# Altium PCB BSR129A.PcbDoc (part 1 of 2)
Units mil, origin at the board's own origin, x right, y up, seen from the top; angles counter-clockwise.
Board outline 2165.87 x 2165.5 mil, 2 copper layers (Top Layer, Bottom Layer), stack 61.2 mil thick; 64 components, 16 nets, 93 pads, 184 vias.
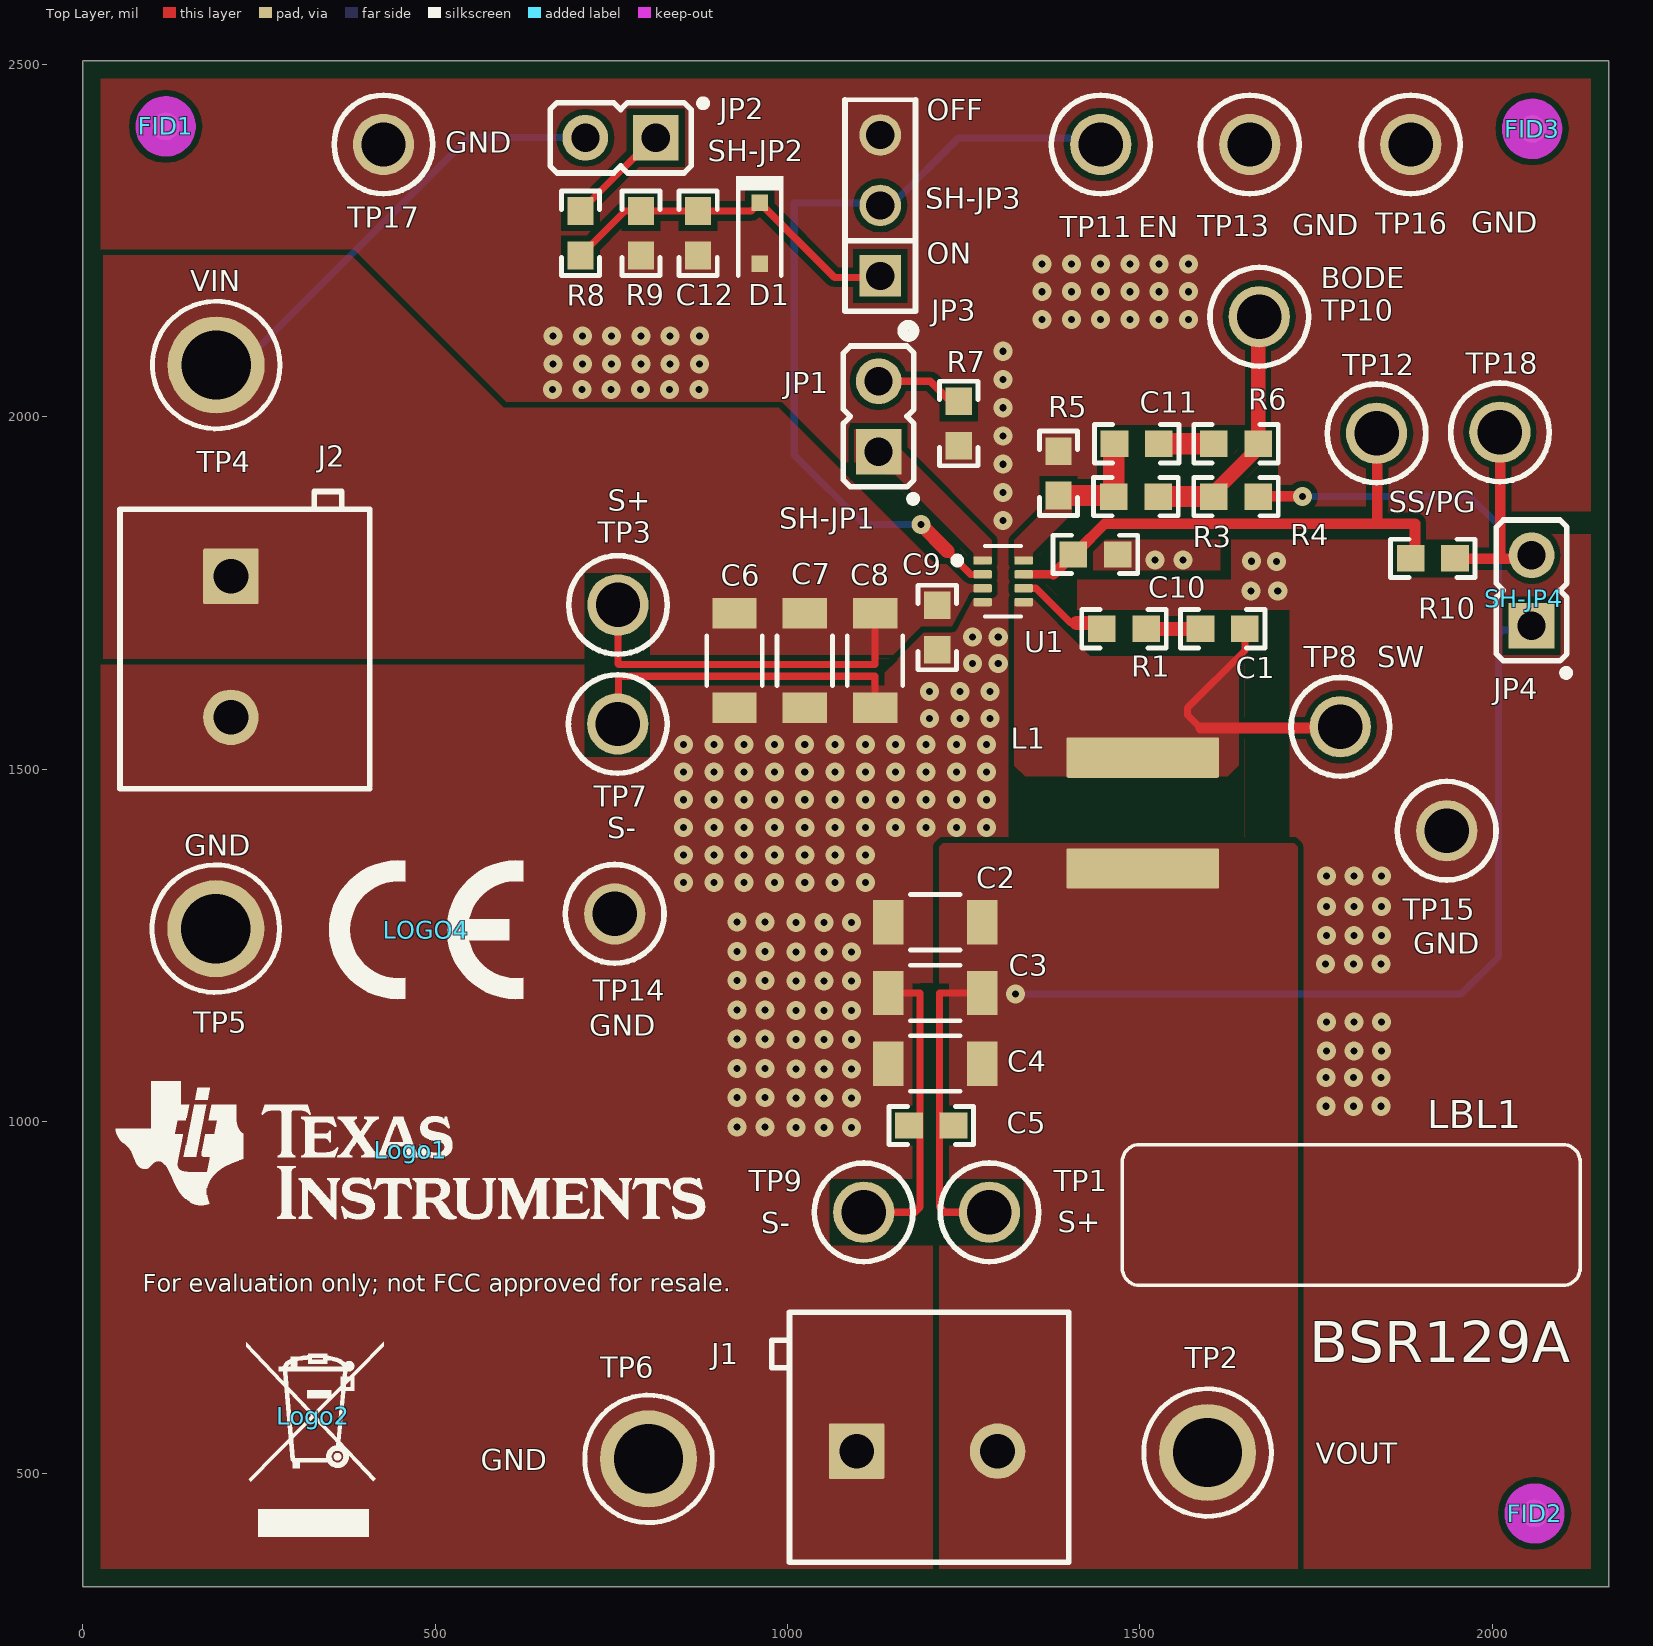
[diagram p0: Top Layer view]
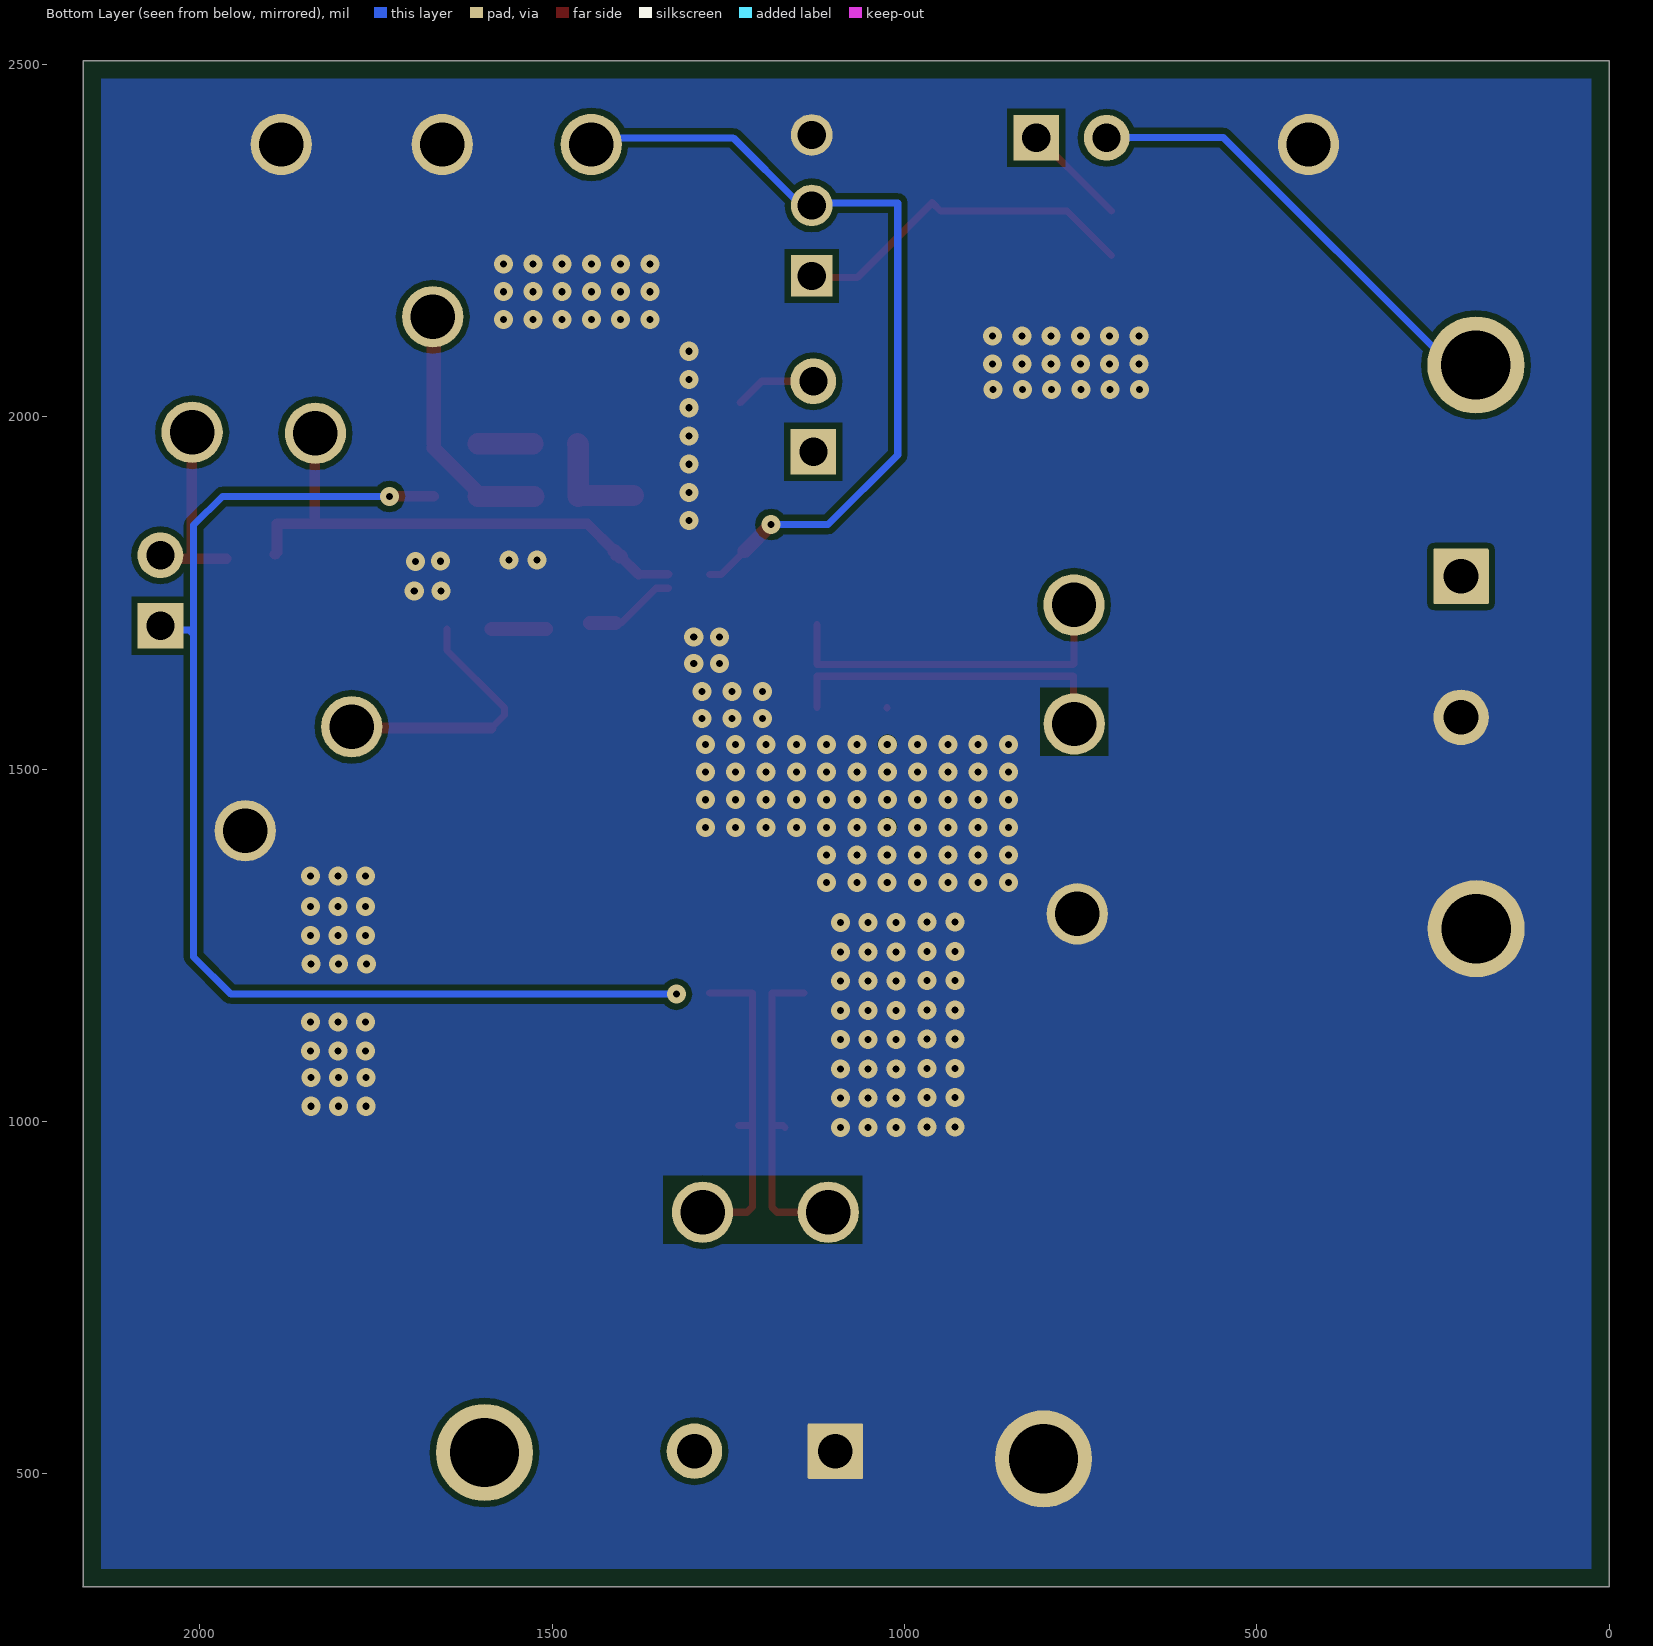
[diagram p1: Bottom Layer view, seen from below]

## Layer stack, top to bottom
Top Solder: solder mask 0.4, Solder Resist, Dk 3.5
Top Layer: signal copper 2.8
Dielectric1: core 55.6, FR-4 High Tg, Dk 4.8
Bottom Layer: signal copper 2.8
Bottom Solder: solder mask 0.4, Solder Resist, Dk 3.5

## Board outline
0,339.65 0,2505 2165.35,2505 2165.35,339.65 2165.87,339.5

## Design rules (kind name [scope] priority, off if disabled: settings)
AcuteAngle [All] p1: minimum=4.50000000000000E+0001 checktracksonly=FALSE
AssemblyTestPointUsage [All] p1: valid=2
BoardOutlineClearance BoardOutlineClearance_MountingHoles [OnCopper and InComponentClass('Mounting Holes')] p1: gap=40 ignorepadtopadclearanceinfootprint=FALSE
BoardOutlineClearance BoardOutlineClearance_Poly [OnCopper and IsPoly] p2: gap=25 ignorepadtopadclearanceinfootprint=FALSE
BoardOutlineClearance [OnCopper and Not InComponentClass('Logo') and not InComponentClass('FiducialMark') and not InRegion(1000,500,4000,800) and not InPoly] p3: gap=75 ignorepadtopadclearanceinfootprint=FALSE
Clearance Clearance_Keepouts [((IsTrack Or IsArc) And Not InPoly) And IsFree and IsKeepOut vs ((IsTrack Or IsArc) And Not InPoly) And IsFree and IsKeepOut] p1: gap=0 ignorepadtopadclearanceinfootprint=FALSE
Clearance Clearance_Poly [InPolygon] p2: gap=8.5 ignorepadtopadclearanceinfootprint=FALSE except(0: Arc-Hole Track-Hole SMDPad-Hole THPad-Hole Via-Hole Fill-Hole Poly-Hole Region-Hole Text-Hole)
Clearance [All] p3: gap=7 ignorepadtopadclearanceinfootprint=FALSE except(0: Arc-Hole Track-Hole SMDPad-Hole THPad-Hole Via-Hole Fill-Hole Poly-Hole Region-Hole Text-Hole)
ComponentClearance ComponentClearance_MountingHoles_FiducialMarks [InComponentClass('Mounting Holes') vs InComponentClass('FiducialMark')] p1: gap=50 collisioncheckmode=3 verticalgap=10 showdistances=FALSE
ComponentClearance ComponentClearance_Shunt [InComponentClass('Header') vs InComponentClass('Shunt')] p2: gap=0 collisioncheckmode=3 verticalgap=0 showdistances=FALSE
ComponentClearance ComponentClearance_Logo [InComponentClass('Logo')] p3: gap=50 collisioncheckmode=3 verticalgap=10 showdistances=FALSE
ComponentClearance ComponentClearance_ScrewToNut [(HasFootprint('NY PMS 440 0025 PH')) vs (HasFootprint('Keystone_1902C'))] p4: gap=5 collisioncheckmode=3 verticalgap=10 showdistances=FALSE
ComponentClearance ComponentClearance_MountingHoles [InComponentClass('Mounting Holes')] p5: gap=250 collisioncheckmode=3 verticalgap=100000 showdistances=FALSE
ComponentClearance ComponentClearance_SmallPassives [HasFootprint('0201*') or HasFootprint('0402*') or HasFootprint('0508') or HasFootprint('0603*') or HasFootprint('0612') or HasFootprint('0805*') or HasFootprint('0815*') or HasFootprint('0830*') or HasFootprint('1206*') or HasFootprint('1210*') or HasFootprint('1808*') or HasFootprint('1812*') or HasFootprint('1825*') or HasFootprint('2010*') or HasFootprint('2220*') or HasFootprint('2225*') or HasFootprint('2512*') or HasFootprint('2728*') or HasFootprint('3518*') vs HasFootprint('0201*') or HasFootprint('0402*') or HasFootprint('0508') or HasFootprint('0603*') or HasFootprint('0612') or HasFootprint('0805*') or HasFootprint('0815*') or HasFootprint('0830*') or HasFootprint('1206*') or HasFootprint('1210*') or HasFootprint('1808*') or HasFootprint('1812*') or HasFootprint('1825*') or HasFootprint('2010*') or HasFootprint('2220*') or HasFootprint('2225*') or HasFootprint('2512*') or HasFootprint('2728*') or HasFootprint('3518*')] p6: gap=14.96 collisioncheckmode=3 verticalgap=10 showdistances=FALSE
ComponentClearance ComponentClearance_THtoSMT [IsThruComponent vs IsSMTComponent] p7: gap=40 collisioncheckmode=3 verticalgap=30 showdistances=FALSE
ComponentClearance ComponentClearance_THtoTH [IsThruComponent vs IsThruComponent] p8: gap=30 collisioncheckmode=3 verticalgap=30 showdistances=FALSE
ComponentClearance [All] p9: gap=30 collisioncheckmode=3 verticalgap=10 showdistances=FALSE
DiffPairsRouting [All] p1: maxlimit=100 minlimit=10 mostfreqgap=10 toplayer_minwidth=15 toplayer_maxwidth=15 toplayer_prefwidth=15 bottomlayer_minwidth=15 bottomlayer_maxwidth=15 bottomlayer_prefwidth=15 maxuncoupledlength=1000
FabricationTestPointUsage TestPointUsage [All] p1: valid=2 allowmultiple=FALSE
FabricationTestpoint Testpoint [All] p1: side=3 testpointundercomponent=TRUE minsize=40 maxsize=100 preferedsize=60 minholesize=0 maxholesize=40 preferedholesize=32 testpointgrid=1 allowsidetop=TRUE allowsidebottom=TRUE usegrid=TRUE gridtolerance=0.01
FanoutControl Fanout_LCC [IsLCC] p1: bgadir=Out bgaviamode=Centered fanoutstyle=Auto fanoutdirection=Alternating viagrid=1 // Fanout_LCC (Default Rule)
FanoutControl Fanout_BGA [IsBGA] p2: bgadir=Out bgaviamode=Centered fanoutstyle=Auto fanoutdirection=Alternating viagrid=1 // Fanout_BGA (Default Rule)
FanoutControl Fanout_Default [All] p4: bgadir=Out bgaviamode=Centered fanoutstyle=Auto fanoutdirection=Alternating viagrid=1 // Fanout_Default (Default Rule)
FanoutControl Fanout_Small [(CompPinCount < 5)] p5: bgadir=Out bgaviamode=Centered fanoutstyle=Auto fanoutdirection=OutThenIn viagrid=1 // Fanout_Small (Default Rule)
HoleSize [All] p1: absolutevalues=TRUE maxlimit=251 minlimit=7.87 maxpercent=80.000 minpercent=20.000
MinimumAnnularRing MinimumAnnularRing_ThermalPadVias [IsVia and InAnyComponent] p1: minimumring=5.91
MinimumAnnularRing [All] p2: minimumring=6
MinimumSolderMaskSliver MinimumSolderMaskSliver_Logo [InComponentClass('Logo') vs InComponentClass('Logo')] p1: minsoldermaskwidth=0.7
MinimumSolderMaskSliver [All] p2: minsoldermaskwidth=3.94
PlaneClearance [All] p1: clearance=0
PlaneConnect [All] p1: planeconnectstyle=Direct reliefexpansion=10 reliefentries=2 reliefconductorwidth=10 reliefairgap=10
PolygonConnect [All] p1: connectstyle=Direct reliefconductorwidth=10 reliefentries=4 polygonreliefangle="90 Angle" airgapwidth=10
RoutingVias ThermalPadVias [IsVia and InAnyComponent] p1: holewidth=7.87 width=19.68 viastyle="Through Hole" minholewidth=7.87 minwidth=19.68 maxholewidth=12.99 maxwidth=23.62
RoutingVias [All] p2: holewidth=16 width=34 viastyle="Through Hole" minholewidth=7.87 minwidth=26 maxholewidth=40 maxwidth=65
SilkToBoardRegionClearance [Not ((IsComment or IsDesignator) And (Hide <> 'False')) and not InRegion(1000,500,4000,800)] p1:
SilkToSilkClearance SilkToSilkClearance_Pb-FreeLogo [(HasFootprint('Pb-Free_Overlay_Medium') OR HasFootprint('Pb-Free_Overlay_Small')) vs (HasFootprint('Pb-Free_Overlay_Medium') OR HasFootprint('Pb-Free_Overlay_Small'))] p1: silktosilkclearance=0
SilkToSilkClearance [All] p2: silktosilkclearance=4
SilkToSolderMaskClearance SilkToComponentPadClearance [(IsPad or IsFill or IsRegion) and InAnycomponent] p1: minsilkscreentomaskgap=2 clearancetoexposedcopper=TRUE
SilkToSolderMaskClearance "Silk to Solder Mask Opening" [All] p2: minsilkscreentomaskgap=0.5 clearancetoexposedcopper=TRUE
SolderMaskExpansion [All] p1: expansion=1.85
Width [All] p1: maxlimit=100 minlimit=3 preferedwidth=10 bottomlayer_minwidth=6 minimp=50.000000 maximp=50.000000 favimp=50.000000 checkconnectedcopper=TRUE
14 further rules are at their usual default settings.

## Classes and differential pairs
component class Label: LBL1
component class Shunt: SH-JP1 SH-JP2 SH-JP3 SH-JP4
component class FiducialMark: FID1 FID2 FID3
component class BSR129A_Hardware: FID1 FID2 FID3 LBL1 Logo1 Logo2 Logo3 LOGO4 LOGO7 SH-JP1 SH-JP2 SH-JP3 SH-JP4 ZZ1 ZZ2 ZZ3 ZZ4
component class Logo: Logo1
component class Header: JP1 JP2 JP3 JP4
component class BSR129A: 2 C1 C2 C3 C4 C5 C6 C7 C8 C9 C11 C12 D1 GND GND3 J1 J2 JP1 JP2 JP3 JP4 L1 R1 R3 R4 R5 R6 R7 R8 R9 R10 TP1 TP2 TP3 TP4 TP5 TP6 TP7 TP8 TP9 TP10 TP11 TP12 TP13 TP14 TP15 TP16 TP17 TP18 U1 VIN1 VOUT0
component class AssemblyNote: ZZ1 ZZ2 ZZ3 ZZ4

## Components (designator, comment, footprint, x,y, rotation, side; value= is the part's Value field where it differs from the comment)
C1 "C0603C104K5RACAUTO" 0603 1617.5,1699 r180 top value=0.1uF
C2 "C3216X5R1V226M160AC" 1206_180 1209.5,1282.5 r180 top value=22uF
C3 "C3216X5R1V226M160AC" 1206_180 1209.5,1182.25 r180 top value=22uF
C4 "C3216X5R1V226M160AC" 1206_180 1209.5,1082 r180 top value=22uF
C5 "C0603C104K5RACAUTO" 0603 1204,994.16 r180 top value=0.1uF
C6 "CGA5L1X7R1H106K160AC" 1206_190 924.75,1653.97 r270 top value=10uF
C7 "CGA5L1X7R1H106K160AC" 1206_190 1024.5,1653.97 r270 top value=10uF
C8 "CGA5L1X7R1H106K160AC" 1206_190 1124.25,1653.97 r270 top value=10uF
C9 "C0603C104K5RACAUTO" 0603 1212.5,1700.98 r270 top value=0.1uF
C10 "06035C333JAT2A" 0603 1437,1804.65 r0 top value=0.033uF
C11 "C0603C100J5GACTU" 0603 1495.47,1961.73 r180 top value=10pF
C12 "C0603C103J5RACTU" 0603 872.9,2260.45 r270 top value=0.01uF
D1 "Zener" SOD-323 960.5,2260.51 r270 top value=5.1V
FID1 "Fiducial" Fiducial10-20 117.37,2412.09 r0 top
FID2 "Fiducial" Fiducial10-20 2060.13,443.5 r0 top
FID3 "Fiducial" Fiducial10-20 2056.63,2408.59 r0 top
J1 "ED120/2DS" On-Shore_ED120_2DS 1198,532 r0 top
J2 "ED120/2DS" On-Shore_ED120_2DS 210,1673.5 r270 top
JP1 "PBC02SAAN" Sullins_PBC02SAAN 1129.27,2000.48 r180 top
JP2 "PBC02SAAN" Sullins_PBC02SAAN 763,2396 r270 top
JP3 "PEC03SAAN" CONN_PEC03SAAN 1131.5,2300 r90 top
JP4 "PBC02SAAN" Sullins_PBC02SAAN 2056,1753.5 r180 top
L1 "74439346068" WE-XHMI_6060 1504,1437.5 r270 top value=6.8uH
LBL1 "THT-14-423-10" Label_650x200 1800,867.16 r0 top
Logo1 "Texas Instruments" TI_Stacked_Overlay_Small 465,959 r0 top
Logo2 "WEEE logo" WEEE_Minimum 327.15,582.5 r0 top
Logo3 "FCC disclaimer" FCC_disclaimer 5235,-1337.5 r90 top
LOGO4 "CE Mark" CE_Mark_5mm 487,1272 r0 top
R1 "RC0603JR-070RL" 0603 1477.5,1699 r0 top value=0
R3 "RC0603FR-0749R9L" 0603 1636.47,1886.73 r0 top value=49.9
R4 "RC0603FR-0753K6L" 0603 1494.48,1886.73 r0 top value=53.6k
R5 "RC0603FR-0710K2L" 0603 1384.48,1919.73 r270 top value=10.2k
R6 "RC0603JR-070RL" 0603 1636.48,1961.73 r0 top value=0
R7 "RC0603JR-070RL" 0603 1243,1990.5 r90 top value=0
R8 "RC0603FR-0749K9L" 0603 706.17,2260.45 r90 top value=49.9k
R9 "RC0603FR-0749K9L" 0603 792,2260.45 r90 top value=49.9k
R10 "RC0603FR-07100KL" 0603 1915.82,1799 r180 top value=100k
SH-JP1 "SNT-100-BK-G" SNT-100-BK-G 1079.27,1941.5 r0 top value=1x2
SH-JP2 "SNT-100-BK-G" SNT-100-BK-G 765.59,2393 r0 top value=1x2
SH-JP3 "SNT-100-BK-G" SNT-100-BK-G 1131,2247 r270 top value=1x2
SH-JP4 "SNT-100-BK-G" SNT-100-BK-G 2045.5,1742.71 r90 top value=1x2
TP1 "VOUT" Keystone5010 1286.5,871 r0 top
TP2 "1502-2" Keystone1502-2 1596,530 r0 top
TP3 "VIN" Keystone5010 759.33,1733 r0 top
TP4 "1502-2" Keystone1502-2 189,2073.5 r0 top
TP5 "1502-2" Keystone1502-2 188.5,1273.5 r0 top
TP6 "1502-2" Keystone1502-2 802.6,521 r0 top
TP7 "GND" Keystone5011 759,1564 r0 top
TP8 "SW" Keystone5014 1784.55,1560 r0 top
TP9 "GND" Keystone5011 1108,871 r0 top
TP10 "Bode" Keystone5014 1669.5,2142 r0 top
TP11 "EN" Keystone5014 1444.5,2386.5 r0 top
TP12 "SS" Keystone5014 1836,1976.5 r0 top
TP13 "GND" Keystone5011 1656,2386.5 r0 top
TP14 "GND" Keystone5011 754.65,1294.5 r0 top
TP15 "GND" Keystone5011 1935.5,1412.5 r0 top
TP16 "GND" Keystone5011 1884.5,2386.5 r0 top
TP17 "GND" Keystone5011 426.5,2386.5 r0 top
TP18 "PG" Keystone5014 2011,1978 r0 top
U1 "TPS62933DRLR" DRL0008A-MFG 1305.87,1766.53 r0 top
ZZ1 "This Assembly Note is for PCB labels only" AssemblyNoteLabel 3685.5,756.5 r0 top
ZZ2 "These assemblies are ESD sensitive, ESD precautions shall be observed." AssemblyNote 3687.5,612 r0 top
ZZ3 "These assemblies must be clean and free from flux and all contaminants. Use of no clean flux is not acceptable." AssemblyNote 3687.5,488.5 r0 top
ZZ4 "These assemblies must comply with workmanship standards IPC-A-610 Class 2., unless otherwise specified." AssemblyNote 3687.5,356 r0 top

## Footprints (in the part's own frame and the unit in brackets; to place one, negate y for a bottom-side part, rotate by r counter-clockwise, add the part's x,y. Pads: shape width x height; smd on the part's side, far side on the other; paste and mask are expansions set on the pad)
0603 [mm] "0603 from SM-752 data"
  rect 1x0.95 smd: 1(-0.8,0) 2(0.8,0)
  silkscreen extent -1.52,-0.69 1.52,0.69, body extent -0.87,-0.47 0.87,0.47, height 1
1206_180 [mm] "1206_180"
  rect 1.1x1.6 smd: 1(-1.7,0) 2(1.7,0)
  silkscreen extent -0.9,-1 0.9,1, body extent -1.75,-0.95 1.75,0.95, height 1.8
1206_190 [mm] "1206_190"
  rect 1.1x1.6 smd: 1(-1.7,0) 2(1.7,0)
  silkscreen extent -0.9,-1 0.9,1, body extent -1.75,-0.95 1.75,0.95, height 1.9
AssemblyNote [mil] "Assembly Note"
AssemblyNoteLabel [mil] "Assembly Note for PCB Labels"
CE_Mark_5mm [mil] "Minimum text height for CE Mark"
  silkscreen extent -138,-98 138,98
CONN_PEC03SAAN [mm] "SULLINS"
  rect 1.5x1.5 hole 1.016: 1(-2.54,0)
  round 1.5 hole 1.016: 2(0,0) 3(2.54,0)
  silkscreen extent -4.72,-1.27 3.81,1.27, body extent -3.84,-1.3 3.84,1.3, height 8.38
DRL0008A-MFG [mm]
  rrect33% 0.67x0.3 smd paste+0 mask+0: 1(-0.74,0.75) 2(-0.74,0.25) 3(-0.74,-0.25) 4(-0.74,-0.75) 5(0.74,-0.75) 6(0.74,-0.25) 7(0.74,0.25) 8(0.74,0.75)
  silkscreen extent -1.77,-1.28 0.65,1.28, body extent -1.17,-1.35 1.17,1.35, height 0.25
FCC_disclaimer [mil]
Fiducial10-20 [mm]
  round 1 smd mask+0.5: 1(0,0)
  Top Layer keep-out circle w1.178: c0,0 r0.5
Keystone1502-2 [mm] "Double Turret"
  round 3.5 hole 2.5: 1(0,0)
  silkscreen extent -2.3,-2.3 2.3,2.3, body extent -1.6,-1.6 1.59,1.6, height 5.62
Keystone5010 [mil] "Keystone Multipurpose loops"
  round 87 hole 63: 1(0,0)
  silkscreen extent -70,-70 70,70, body extent -63,-63 63,62, height 319
Keystone5011 [mil] "Keystone Multipurpose loops"
  round 87 hole 63: 1(0,0)
  silkscreen extent -70,-70 70,70, body extent -63,-63 63,62, height 319
Keystone5014 [mil] "Keystone Multipurpose loops"
  round 87 hole 63: 1(0,0)
  silkscreen extent -70,-70 70,70, body extent -63,-63 63,62, height 319
Label_650x200 [mil] "Thermal Transfer Label"
  round 1 on Mech13: 0(0,0)
  silkscreen extent -325,-100 325,100, body extent -325,-100 325,100, height 1
On-Shore_ED120_2DS [mm] "ONSHORE"
  rrect5% 2x2 hole 1.25: 1(-2.54,0)
  round 2 hole 1.25: 2(2.54,0)
  silkscreen extent -5.6,-4 5.12,5, body extent -5.78,-4 5.08,5, height 13
SNT-100-BK-G [mil] "Samtec STEP model"
  round 1 on Mech3: 0(0,0)
  body extent -100,-50 100,50, height 344
SOD-323 [mm] "NXP recommended land pattern"
  rect 0.6x0.6 smd paste-0.05: 1(-1.1,0) 2(1.1,0)
  silkscreen extent -2.06,-0.86 1.53,0.86, body extent -1.3,-0.67 1.3,0.68, height 1.1
Sullins_PBC02SAAN [mm] "Sullins 100mil, 1x2, 230 mil above insulator"
  rect 1.65x1.65 hole 1.016: 1(0,1.27)
  round 1.65 hole 1.016: 2(0,-1.27)
  silkscreen extent -1.37,-2.54 1.27,3.1, body extent -1.27,-2.54 1.27,2.54, height 8.38
TI_Stacked_Overlay_Small [mil]
  silkscreen extent -418,-98 418,98
WE-XHMI_6060 [mm] "SMD, 2-Leads, Body 6.65x6.45mm"
  rrect7% 1.45x5.5 smd: 1(-2,0) 2(2,0)
  body extent -3.23,-3.32 3.22,3.33, height 5.78
WEEE_Minimum [mil] "WEEElie bin"
  silkscreen extent -95,-172 99,104

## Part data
C1 C5 C9: library part CMP-0079602-1, "CAP, CERM, 0.1 µF, 50 V,+/- 10%, X7R, AEC-Q200 Grade 1, 0603", Cap_Case=0603, Manufacturer=Kemet, Supplier Part Number 1=399-6856-1-ND, TempCo=X7R, Tolerance_%=10%, Value2=50V, ValueDisplayed=0.1µF
C2 C3 C4: library part CMP-0008667-2, "CAP, CERM, 22 uF, 35 V, +/- 20%, X5R, 1206", Cap_Case=1206_180, Manufacturer=TDK, Supplier Part Number 1=445-8045-1-ND, TempCo=X5R, Tolerance_%=20%, Value1="0.002398 ohm", Value2=35V, ValueDisplayed=22uF
C6 C7 C8: library part CMP-0085950-1, "CAP, CERM, 10 µF, 50 V,+/- 10%, X7R, AEC-Q200 Grade 1, 1206", Cap_Case=1206, Manufacturer=TDK, TempCo=X7R, Tolerance_%=10%, Value2=50V, ValueDisplayed=10µF
C10: library part CMP-0006806-1, "CAP, CERM, 0.033 uF, 50 V, +/- 5%, X7R, 0603", Cap_Case=0603, Manufacturer=AVX, Supplier Part Number 1=478-3723-1-ND, TempCo=X7R, Tolerance_%=5%, Value1=Unknown, Value2=50V, ValueDisplayed=0.033uF
C11: library part CMP-0006839-4, "CAP, CERM, 10 pF, 50 V, +/- 5%, C0G/NP0, 0603", Cap_Case=0603, Manufacturer=Kemet, Supplier Part Number 1=399-1049-1-ND, TempCo=C0G/NP0, Tolerance_%=5%, Value1=Unknown, Value2=50V, ValueDisplayed=10pF
C12: library part CMP-0006850-4, "CAP, CERM, 0.01 uF, 50 V, +/- 5%, X7R, 0603", Cap_Case=0603, Manufacturer=Kemet, Supplier Part Number 1=399-1092-1-ND, TempCo=X7R, Tolerance_%=5%, Value1=Unknown, Value2=50V, ValueDisplayed=0.01uF
D1: library part CMP-0005854-3, "Diode, Zener, 5.1 V, 200 mW, SOD-323", Manufacturer="Diodes Inc.", PartNumber=MMSZ5231BS-7-F, Power_W=200mW, Value1=0.2W
FID1 FID2 FID3: library part CMP-0077181-1, "Fiducial mark.  There is nothing to buy or mount.", Manufacturer=N/A
J1 J2: library part CMP-0074910-1, "Terminal Block, 5.08 mm, 2x1, Brass, TH", Color=Blue, Current_A=15A, Manufacturer="On-Shore Technology", Supplier Part Number 1=ED1609-ND, Voltage_V=300V
JP1 JP2 JP4: library part CMP-0054566-1, "Header, 100mil, 2x1, Gold, TH", Color=Black, Current_A=3A, Manufacturer="Sullins Connector Solutions", Supplier Part Number 1=S1011E-02-ND, Voltage_V=1.8kV
JP3: library part CMP-0002338-1, "Header, 100mil, 3x1, Tin, TH", Color=Black, Current_A=3A, Manufacturer="Sullins Connector Solutions", Supplier Part Number 1=S1012E-03-ND, Voltage_V=1.8kV
L1: library part CMP-0085369-1, "Inductor, Shielded, Hyperflux, 6.8 µH, 6.5 A, 0.01936 ohm, SMD", Manufacturer="Wurth Elektronik", Value1="0.01936 ohm", Value2=6.5A, ValueDisplayed=6.8µH
LBL1: library part CMP-0003625-1, "Thermal Transfer Printable Labels, 0.650\" W x 0.200\" H - 10,000 per roll", Manufacturer=Brady, Supplier Part Number 1=97C5133
Logo1: library part CMP-0074838-1, "Texas Instrument Corporate Signature"
Logo2: library part CMP-0074769-1
Logo3: library part CMP-0074847-1, "FCC_disclaimer"
LOGO4: library part CMP-0074844-1
R1 R6 R7: library part CMP-0025885-5, "RES, 0, 5%, 0.1 W, 0603", Manufacturer=Yageo, Power_W=100mW, Supplier Part Number 1=311-0.0GRCT-ND, TempCo="200 ppm/C", Tolerance_%=5%, Value2=0.1W, Value_Code=0000, ValueDisplayed=0
R3: library part CMP-0023143-5, "RES, 49.9, 1%, 0.1 W, 0603", Manufacturer=Yageo, Power_W=100mW, Supplier Part Number 1=311-49.9HRCT-ND, TempCo="100 ppm/C", Tolerance_%=1%, Value2=0.1W, Value_Code=49R9, ValueDisplayed=49.9
R4: library part CMP-0023176-5, "RES, 53.6 k, 1%, 0.1 W, 0603", Manufacturer=Yageo, Power_W=100mW, Supplier Part Number 1=311-53.6KHRCT-ND, TempCo="100 ppm/C", Tolerance_%=1%, Value2=0.1W, Value_Code=53k6, ValueDisplayed=53.6k
R5: library part CMP-0022743-5, "RES, 10.2 k, 1%, 0.1 W, 0603", Manufacturer=Yageo, Power_W=100mW, Supplier Part Number 1=311-10.2KHRCT-ND, TempCo="100 ppm/C", Tolerance_%=1%, Value2=0.1W, Value_Code=10k2, ValueDisplayed=10.2k
R8 R9: library part CMP-0023142-5, "RES, 49.9 k, 1%, 0.1 W, 0603", Manufacturer=Yageo, Power_W=100mW, Supplier Part Number 1=311-49.9KHRCT-ND, TempCo="100 ppm/C", Tolerance_%=1%, Value2=0.1W, Value_Code=49k9, ValueDisplayed=49.9k
R10: library part CMP-0022735-5, "RES, 100 k, 1%, 0.1 W, 0603", Manufacturer=Yageo, Power_W=100mW, Supplier Part Number 1=311-100KHRCT-ND, TempCo="100 ppm/C", Tolerance_%=1%, Value2=0.1W, Value_Code=100k
SH-JP1 SH-JP2 SH-JP3 SH-JP4: library part CMP-0003623-3, "Shunt, 100mil, Gold plated, Black", Alternate Manufacturer=3M, Alternate PartNumber=969102-0000-DA, Manufacturer=Samtec, Supplier Part Number 1=SAM8858-ND
TP1 TP3: library part CMP-0055147-1, "Test Point, Multipurpose, Red, TH", Color=Red, Manufacturer=Keystone, PartNumber=5010, Supplier Part Number 1=36-5010-ND
TP2 TP4 TP5 TP6: library part CMP-0055113-1, "Terminal, Turret, TH, Double", Manufacturer=Keystone, Supplier Part Number 1=36-1502-2-ND
TP7 TP9 TP13 TP14 TP15 TP16 TP17: library part CMP-0055148-1, "Test Point, Multipurpose, Black, TH", Color=Black, Manufacturer=Keystone, PartNumber=5011, Supplier Part Number 1=36-5011-ND
TP8 TP10 TP11 TP12 TP18: library part CMP-0055151-1, "Test Point, Multipurpose, Yellow, TH", Color=Yellow, Manufacturer=Keystone, PartNumber=5014, Supplier Part Number 1=36-5014-ND
U1: library part CMP-0090998-1, "3.8-V to 30-V Input, 3-A/2-A, 300kHz-2.2MHz, Low IQ Synchronous Buck Converter in SOT583 Package", Manufacturer="Texas Instruments", Max Supply Voltage=30V, Min Supply Voltage=3.8V, Nominal Supply Current=12-250uA, Operating Temperature Range="-40°C to +150°C", Output Voltage=0.8-22V, Switching Frequency=310-2100kHz
ZZ1: library part CMP-0003616-3
ZZ2: library part CMP-0077236-1
ZZ3: library part CMP-0077237-1
ZZ4: library part AssemblyNote

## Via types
v1: diameter 27, hole 10, Top Layer to Bottom Layer, 184 vias

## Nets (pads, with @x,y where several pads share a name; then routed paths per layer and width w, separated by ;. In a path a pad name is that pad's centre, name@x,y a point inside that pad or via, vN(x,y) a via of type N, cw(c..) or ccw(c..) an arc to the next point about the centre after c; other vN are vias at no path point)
BST: R1.1 U1.6 | length 131.4
  Top Layer w10: U1.6@1335,1756.69 1352.81,1756.69 1402,1707.5 1410.5,1707.5
  Top Layer w20: 1410.5,1707.5 R1.1@1446,1707.5
EN: JP3.2 TP11.1 U1.2 | length 1173.2
  Top Layer w10: 1226.66,1809.66 1259.96,1776.37 U1.2@1276.73,1776.37
  Top Layer w20: v1(1189.33,1847) 1226.66,1809.66
  Bottom Layer w10: v1(1189.33,1847) 1108.3,1847 1009.5,1945.8 1009.5,2303.5 1131.5,2303.5 1132.5,2302.5 1149.5,2302.5 1243,2396 1435,2396 TP11.1@1444.5,2386.5
FB: C11.2 R4.1 R5.2 U1.8 | length 154.5
  Top Layer w30: R5.2@1384.48,1888.23 1461.49,1888.23 R4.1@1462.99,1886.73 1462.99,1960.74 C11.2@1463.98,1961.73
GND: C2.2 C3.2 C4.2 C5.2 C6.2 C7.2 C8.2 C9.2 C10.2 C12.2 D1.2 J1.1 J2.2 JP3.3 R5.1 R7.1 R9.1 TP5.1 TP6.1 TP7.1 TP9.1 TP13.1 TP14.1 TP15.1 TP16.1 TP17.1 U1.4 | length 964.9
  Top Layer w10: TP7.1@760,1529 760,1631.75 1124,1631.75 C8.2@1124,1587.54 ; C7.2@1024.5,1587.04 C7.2@1025,1587.54 ; TP9.1@1108,871 1180.88,871 1188.25,878.37 1188.25,1182.25 C3.2@1142.57,1182.25 ; C5.2@1169.69,991.35 C5.2@1172.5,994.16 C5.2@1187.91,994.16
  Bottom Layer w10: v1@1024.01,1535.35 v1(1024.36,1535) ; v1@1024.06,1417.6 v1(1024.41,1417.25)
  other v1: 1012,991.35 1051.5,991.35 1091,991.35 928.5,992.15 968,992.15 1764,1021.48 1803.25,1021.48 1842.5,1021.48 1012,1032.88 1051.5,1032.88 1091,1032.88 928.5,1033.69 968,1033.69 1764,1062.5 1803.25,1062.5 1842.5,1062.5 1012,1074.42 1051.5,1074.42 1091,1074.42 928.5,1075.23 968,1075.23 1764.75,1099.93 1804,1099.93 1843.25,1099.93 1012,1115.96 1051.5,1115.96 1091,1115.96 928.5,1116.77 968,1116.77 1764.75,1140.95 1804,1140.95 1843.25,1140.95 928.5,1158.31 968,1158.31 1012,1157.5 1051.5,1157.5 1091,1157.5 1012,1199.04 1051.5,1199.04 1091,1199.04 928.5,1199.85 968,1199.85 1763.75,1223.55 1803,1223.55 1842.25,1223.55 928.5,1241.39 968,1241.39 1012,1240.58 1051.5,1240.58 1091,1240.58 1764.75,1264.02 1804,1264.02 1843.25,1264.02 1012,1282.12 1051.5,1282.12 1091,1282.12 928.5,1282.93 968,1282.93 1764.75,1305.05 1804,1305.05 1843.25,1305.05 852.32,1338.75 895.34,1338.75 938.36,1338.75 981.39,1338.75 1024.41,1338.75 1067.43,1338.75 1110.45,1338.75 1764.75,1348.55 1804,1348.55 1843.25,1348.55 852.32,1378 895.34,1378 938.36,1378 981.39,1378 1024.41,1378 1067.43,1378 1110.45,1378 852.32,1417.25 895.34,1417.25 938.36,1417.25 981.39,1417.25 1067.43,1417.25 1110.45,1417.25 1153.48,1417.25 1196.5,1417.25 1239.52,1417.25 1282.55,1417.25 852.27,1456.5 895.3,1456.5 938.32,1456.5 981.34,1456.5 1024.36,1456.5 1067.39,1456.5 1110.41,1456.5 1153.43,1456.5 1196.45,1456.5 1239.48,1456.5 1282.5,1456.5 852.27,1495.75 895.3,1495.75 938.32,1495.75 981.34,1495.75 1024.36,1495.75 1067.39,1495.75 1110.41,1495.75 1153.43,1495.75 1196.45,1495.75 1239.48,1495.75 1282.5,1495.75 852.27,1535 895.3,1535 938.32,1535 981.34,1535 1067.39,1535 1110.41,1535 1153.43,1535 1196.45,1535 1239.48,1535 1282.5,1535 1201.45,1572 1244.48,1572 1287.5,1572 1201.45,1610.25 1244.48,1610.25 1287.5,1610.25 1262.48,1650 1299.02,1650 1262.48,1687.25 1299.02,1687.5 1695.72,1752.5 1657.5,1752.73 1694,1794.5 1658.5,1795 1561,1796.5 1521.48,1796.77 1305.5,1852.5 1305.5,1892.59 1305.5,1932.67 1305.5,1972.76 1305.5,2012.85 666.46,2039 708,2039 749.54,2039 791.08,2039 832.62,2039 874.15,2039 1305.5,2052.94 667.31,2074.95 708.85,2074.95 750.38,2074.95 791.92,2074.95 833.46,2074.95 875,2074.95 1305.5,2093.02 667.31,2114.45 708.85,2114.45 750.38,2114.45 791.92,2114.45 833.46,2114.45 875,2114.45 1361.31,2138 1402.85,2138 1444.38,2138 1485.92,2138 1527.46,2138 1569,2138 1361.31,2177.5 1402.85,2177.5 1444.38,2177.5 1485.92,2177.5 1527.46,2177.5 1569,2177.5 1361.31,2217 1402.85,2217 1444.38,2217 1485.92,2217 1527.46,2217 1569,2217
NetC1_2: C1.2 R1.2 | length 77
  Top Layer w20: R1.2@1508.99,1699 C1.2@1586,1699
NetC11_1: C11.1 R6.1 | length 78
  Top Layer w30: C11.1@1526.97,1961.73 R6.1@1604.99,1961.73
NetC12_1: C12.1 D1.1 JP3.1 R8.1 R9.2 | length 486.2
  Top Layer w10: R8.1@706.17,2228.95 769.16,2291.94 R9.2@792,2291.94 C12.1@872.9,2291.94 948.63,2291.94 D1.1@960.5,2303.81 1066.31,2198 JP3.1@1117.5,2198
NetJP1_2: JP1.2 R7.2 | length 135.2
  Top Layer w10: JP1.2@1120,2073.5 1143.02,2050.48 1202.51,2050.48 R7.2@1233,2019.99
NetJP2_1: JP2.1 R8.2 | length 172.3
  Top Layer w10: R8.2@706.17,2291.94 JP2.1@828,2413.77
NetJP4_2: JP4.2 R10.1 TP18.1 | length 254.2
  Top Layer w15: R10.1@1962.5,1798.5 2011.5,1798.5 ; TP18.1@2011.5,1955.98 2011.5,1798.5 ; JP4.2@2058,1801.5 2055,1798.5 2011.5,1798.5
NetR3_1: R3.1 R4.2 R6.2 TP10.1 | length 337.1
  Top Layer w10: R3.1@1604.98,1886.73 R3.1@1604.98,1892.98 ; R6.2@1667.98,1955.98 R6.2@1667.98,1961.73
  Top Layer w20: R3.1@1604.98,1892.98 R6.2@1667.98,1955.98 ; R6.2@1667.98,1961.73 1667.98,2117.98 TP10.1@1668.5,2118.5
  Top Layer w30: R4.2@1525.98,1886.73 R3.1@1604.98,1886.73
RT: JP1.1 U1.1
SS: C10.1 R10.2 TP12.1 U1.7 | length 738.8
  Top Layer w10: C10.1@1411.5,1801.13 C10.1@1412.13,1801.13 ; 1836,1848 1837,1849
  Top Layer w12: U1.7@1335,1776.37 1377.37,1776.37
  Top Layer w15: 1377.37,1776.37 C10.1@1402.5,1801.5 ; C10.1@1411.51,1809.5 1450.01,1848 1836,1848 1890.5,1848 1890.5,1807.51 R10.2@1893.39,1804.62 ; 1837,1849 TP12.1@1837,1955.98
  Top Layer w20: C10.1@1402.5,1801.5 1403.51,1801.5 C10.1@1411.51,1809.5
SW: C1.1 L1.1 TP8.1 U1.5 | length 404
  Top Layer w10: 1586.21,1558.31 1567.5,1577.02 1567.5,1587 1648.99,1668.49 C1.1@1648.99,1699
  Top Layer w15: 1586.21,1558.31 TP8.1@1808,1558.31
VIN: C6.1 C7.1 C8.1 C9.1 J2.1 JP2.2 TP3.1 TP4.1 U1.3 | length 1163.1
  Top Layer w10: TP3.1@759.33,1733 759.33,1649.23 759.81,1648.75 1124.25,1648.75 C8.1@1124.25,1705.13
  Bottom Layer w10: TP4.1@189,2073.5 224.5,2073.5 547.5,2396.5 JP2.2@713,2396.5
VOUT: C2.1 C3.1 C4.1 C5.1 J1.2 JP4.1 L1.2 R3.2 TP1.1 TP2.1 | length 2210.6
  Top Layer w10: C5.1@1235.5,994.16 1215.84,994.16 1215.5,994.5 ; C3.1@1276.43,1182.25 1215.5,1182.25 1215.5,994.5 ; TP1.1@1286.5,871 1223.34,871 1215.5,878.84 1215.5,994.5 ; R3.2@1667.97,1886.73 R3.2@1668.24,1887
  Top Layer w15: R3.2@1668.24,1887 v1(1731,1887)
  Bottom Layer w10: v1(1323.76,1180.5) 1956,1180.5 2008.79,1233.29 2008.79,1691 ; v1(1731,1887) 1968,1887 2008.79,1846.21 2008.79,1691 ; JP4.1@2080.5,1697.1 2014.89,1697.1 2008.79,1691
pads on no net: FID1.1 FID2.1 FID3.1 LBL1.0 SH-JP1.0 SH-JP2.0 SH-JP3.0 SH-JP4.0

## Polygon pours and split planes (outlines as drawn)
GND on Bottom Layer "Bottom Layer-GND" (solid, pour order 157): -102.5,2537.5 -102.5,292.5 2227.5,292.5 2227.5,2537.5
no net on Bottom Layer "BOTTOM_LAYER_NONET_P106" (solid, remove dead copper, pour order 106): -38.5,1953.5
GND on Top Layer "Top Layer-GND" (solid, pour order 153): -53.5,2550.5 2194.5,2550.5 2194.5,282 2176.5,264 -53.5,264
VOUT on Top Layer "Top Layer-VOUT" (solid, pour order 151): 1724,360 1719,355 1219.5,355 1215,359.5 1215,1390 1220,1395 1719,1395 1724,1390
no net on Top Layer "Top Layer-No Net" (solid, pour order 149): 1676.5,355
no net on Top Layer "Top Layer-No Net 1" (solid, pour order 147): 1205,365
no net on Top Layer "TOP_LAYER_NONET_P145" (solid, remove dead copper, pour order 145): 1632,1760.8
FB on Top Layer "TOP_LAYER_FB_P143" (solid, remove dead copper, pour order 143): 1322,1790.5 1348,1790.5 1348,1807 1403.18,1862.18 1403.18,1879 1376,1879 1322,1825
RT on Top Layer "TOP_LAYER_RT_P139" (solid, remove dead copper, pour order 139): 1289.5,1790.5 1264,1790.5 1264,1806.5 1152,1918.5 1095,1918.5 1095,1982.5 1160.5,1982.5 1160.5,1954 1289.5,1825
VIN on Top Layer "TOP_LAYER_VIN_P132" (solid, remove dead copper, pour order 132): 1259.12,1751 1290,1751 1290,1762.5 1263.63,1762.5 1235.13,1791 1209.5,1791 987.5,2013 597,2013 429.5,2180.5 381,2229 28.5,2229 28.5,1656.5 1144,1656.5 1190,1702.5 1233.15,1702.5
SW on Top Layer "TOP_LAYER_SW_P118" (solid, remove dead copper, pour order 118): 1322,1743 1322,1505 1337,1490 1625,1490 1640.5,1505.5 1640.5,1655 1635,1660.5 1429.5,1660.5 1347,1743
no net on Top Solder (solid): 1373.28,1490 1373.28,1599 1637,1599 1637,1490
no net on Top Solder (solid): 1373.5,1395.5 1636.41,1395.5 1636.41,1193.5 1373.5,1193.5
no net on Top Solder "NONET_L-01_P-001" (solid, remove dead copper): 1289.5,1790

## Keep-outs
Keep-Out Layer:
  text ".Layer_Name" at 570,-868.49 h60

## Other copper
Top Layer:
  pour cut-out: 1229.26,1195.96 1207.63,1195.96 1197.91,1186.24 1197.91,919.5 1197.25,918.84 1229.26,918.84
  pour cut-out: 1201.5,1022.7 1201.5,1196 1177,1196 1177,918.51 1177.46,918.05 1178.25,918.84 1201.74,918.84
  pour cut-out: 2027.5,1866.28 2027.81,1865.96 2027.81,1833.53 2144.03,1833.53 2145,1834.5 2145,1864.78 2146.5,1866.28
  pour cut-out: 1156.15,1656.39 1156.15,1654.65 1137.41,1635.91 1136.22,1635.91 1136.22,1652.46 1135.5,1653.18
  pour cut-out: 1138.01,1632
  pour cut-out: 1138.01,1639.91
  pour cut-out: 1125.5,1639.91 1138.01,1639.91 1138.01,1618 1126.5,1618 1125.5,1619
  pour cut-out: 805,1640.98 1118.98,1640.98 1119,1641 1119,1617.98 805.18,1617.98
  pour cut-out: 805.18,1628
  pour cut-out: 1129.27,1656.5 1129.27,1662.52 1150.13,1662.52 1144.11,1656.5 1144,1656.5
  pour cut-out: 1110.48,1662.51 1119.49,1662.51 1119.5,1662.52 1119.5,1656.5 1110.48,1656.5
  pour cut-out: 801.5,1662.51 1110.48,1662.51 1110.48,1654.02 801.5,1654
  pour cut-out: 1188.25,1196.01 1188.35,1195.91 1206.33,1195.91 1206.96,1195.29 1206.96,1188.03 1201.88,1182.95
  pour cut-out: 1142.98,1022.7 1265.02,1022.7 1265.02,965.62 1145.3,965.62 1144.02,966.9
  pour cut-out: 1164.5,1295.06
  pour cut-out: 1137.76,1631.75 1138.01,1632 1138.01,1647.83 1137.87,1647.83 1137.84,1647.87 1134.97,1645 1132.84,1645 1132.84,1641.91 1134.68,1640.06
  pour cut-out: 1439.69,1769 1411.23,1769 1410.98,1769.25 1410.98,1782.3 1439.69,1782.3
  pour cut-out: 1439.69,1782.3 1613.89,1782.3 1614.18,1827 1630,1827 1630,1769 1439.69,1769
  pour cut-out: 1367.73,1761.23 1371.33,1764.83 1388.91,1764.83 1406.38,1782.3 1410.98,1782.3 1410.98,1726.84 1409.19,1725.05 1403.91,1725.05
  pour cut-out: 1076.83,1939 1076.83,1935.5 1168.58,1843.76 1190.13,1868.11 1122.74,1935.5 1082.5,1935.5
  pour cut-out: 1244.77,1813.48 1255.33,1802.91 1255.33,1801.14 1254.99,1800.8 1245.38,1810.42
  pour cut-out: 1713,1572.07 1713,1726.2 1677.18,1726.2 1677.18,1671.8 1662.76,1671.8 1649.17,1658.17 1649.17,1572.07
  pour cut-out: 1713,1398.5 1713,1544.5 1649.21,1544.5 1649.17,1403.83 1654.17,1398.5
  pour cut-out: 1912.51,1826.2 1919.13,1826.2 1919.13,1771.8 1912.51,1771.8
  pour cut-out: 1383.32,1830.07 1383.32,1803.07 1370.38,1790.13 1356.5,1790.13 1356.67,1803.41
  pour cut-out: 1404.64,1825.7 1438.47,1859.53 1434.8,1859.53 1434.8,1864.27 1411.85,1864.27 1373.27,1825.7
  pour cut-out: 1652.61,1913.93 1696.16,1913.93 1696.16,1913.94 1696.16,1934.53 1673.21,1934.53
  pour cut-out: 1639.79,1954.47 1633.17,1947.85 1633.17,1988.93 1639.79,1988.93
  pour cut-out: 1492.16,1988.93 1498.79,1988.93 1498.79,1934.53 1555.16,1934.53 1555.16,1937.77 1576.8,1937.77 1576.8,1934.53 1619.86,1934.53 1599.26,1913.93 1576.79,1913.93 1576.79,1910.69 1554.16,1910.69 1553.5,1911.36 1553.5,1914 1497.86,1914 1497.79,1913.93 1497.79,1864.31 1491.17,1864.31 1491.17,1913.93 1486.95,1913.93 1486.95,1934.53 1492.16,1934.53
  pour cut-out: 1633.16,1864.31 1633.16,1894.49 1639.79,1901.11 1639.79,1864.31
  pour cut-out: 1696.16,1873.24 1824,1873.24 1823.24,1872.47 1823.24,1864.31 1696.16,1864.31
  pour cut-out: 1447,1826
  pour cut-out: 1456,1825.5 1450.36,1825.5 1450.16,1825.7 1456.15,1831.69 1456.77,1831.69 1456.77,1826.27
  pour cut-out: 1883.19,1825.7 1883.19,1831.69 1456.77,1831.69 1456.77,1826.27 1456,1825.5
  pour cut-out: 1620.81,1680.14 1620.81,1726.2 1614.18,1726.2 1614.18,1680.14
  pour cut-out: 1480.81,1676.5 1480.81,1726.2 1474.18,1726.2 1474.18,1676.5
  pour cut-out: 1413.62,1688.64 1417.82,1688.64 1417.82,1684.44
  pour cut-out: 1429,1676.5 1533.54,1676.5 1537.18,1680.14 1635.86,1680.14 1636.5,1679.5 1636.5,1667 1635.5,1666 1427,1666
  pour cut-out: 1649,1482.5 1649,1513.5 1617.5,1482
  pour cut-out: 1313.33,1482.5 1313.33,1515.46 1315.87,1518 1316.5,1517.37 1316.5,1507 1341.5,1482
  pour cut-out: 1313.33,1482.5 1649,1482.5 1649,1397 1313.33,1397
  pour cut-out: 1335,823.5 1059.5,823.5 1059.5,918.84 1335,918.84
  pour cut-out: 805.18,1516.5 711.76,1516.5 711.76,1778.5 805.18,1778.5
  text ".Layer_Name" at 570,-868.49 h60
Bottom Layer:
  pour cut-out: 1342,826.5 1059.63,826.5 1059.63,923 1342,923.01
  pour cut-out: 806.92,1519 710.5,1519 710.5,1615.5 806.92,1615.5
  text ".Layer_Name" at 570,-868.49 h60

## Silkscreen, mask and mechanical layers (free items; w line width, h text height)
Top Overlay:
  text "OFF" at 1197.79,2421 h30
  text "GND" at 514.5,2375 h30
  text "GND" at 1970,2261.5 h30
  text "GND" at 1716.5,2257.5 h30
  text "EN" at 1497.79,2255 h30
  text "ON" at 1197.79,2217.5 h30
  text "BODE" at 1757,2182.5 h30
  text "VIN" at 152,2178 h30
  text "S+" at 745,1866.5 h30
  text "SS/PG" at 1853.31,1864.31 h30
  text "SW" at 1837,1644.18 h30
  text "S-" at 744,1402 h30
  text "GND" at 143.53,1377 h30
  text "GND" at 1888,1238 h30
  text "GND" at 718.59,1121.5 h30
  text "S-" at 962.5,841.5 h30
  text "S+" at 1383.5,842.44 h30
  text "BSR129A" at 1740.5,639 h100
  text "VOUT" at 1749.5,514 h30
  text "GND" at 564.5,505 h30
  text ".Layer_Name" at 570,-868.49 h30
Bottom Overlay:
  text ".Layer_Name" at 570,-868.49 h60
Top Paste:
  text ".Layer_Name" at 570,-868.49 h60
Bottom Paste:
  text ".Layer_Name" at 570,-868.49 h60
Top Solder:
  text ".Layer_Name" at 570,-868.49 h60
  text ".Layer_Name" at 570,-868.49 h60
Bottom Solder:
  text ".Layer_Name" at 570,-868.49 h60
Drill Guide:
  text ".Layer_Name" at 570,-868.49 h60
M1 Board Outline:
  lines w10: 0,339.65 0,2505 2165.35,2505 2165.35,339.65 ; 0.52,339.5 2165.87,339.5
  text ".Layer_Name" at 570,-868.49 h60
M2 Board Dimensions:
  rectangle: 118,-410 493,-285
  rectangle: -7,-285 118,-160
  lines w7: -7,-285 993,-285 ; 118,-410 118,-160 ; 243,-410 243,-160 ; 493,-410 493,-160 ; 743,-410 743,-160 ; -7,-410 -7,-160 993,-160 993,-410 -7,-410
  text ".Layer_Name" at 570,-868.49 h60
M3 3D STEP Top:
  text ".Layer_Name" at 570,-868.49 h60
M4 3D STEP Bottom:
  text ".Layer_Name" at 570,-868.49 h60
M5 Assembly Top:
  lines w10: -299,-940.17 6301,-940.17 ; -299,-736.83 6303,-736.83 ; -299,-533.5 -299,-1143.5 3706,-1143.5 6303,-1143.5 6303,-533.5 -298.5,-533.5 -298.5,-1143.5 1277,-1143.5 ; 2166,-1143.5 2166,-533.5 ; 3433,-736.83 3433,-533.5 ; 4273,-736.83 4273,-533.5 ; 4895,-1150 4895,-947.17
  text "COMPONENTS MARKED 'DNP' SHOULD NOT BE POPULATED." at 1146.5,-328.5 h60
  text "ASSEMBLY VARIANT:" at 1146,-444 h60
  text ".VariantName" at 2182,-444 h60
  text "PCB VIEWED FROM TOP SIDE" at -235.5,-665.67 h60
  text "BOARD #:" at 2241,-665.67 h60
  text ".PRJ_Number" at 2786.5,-665.67 h60
  text "REV:" at 3631,-665.67 h60
  text ".PCB_Rev" at 3922.5,-665.67 h60
  text "SVN REV:" at 4469,-665.67 h60
  text ".VersionControl_RevNumber" at 4975,-665.67 h60
  text "TID #:" at 2241,-869 h60
  text ".TID" at 2786.5,-869 h60
  text "PLOT NAME =" at -235.5,-1074.34 h60
  text ".plot_File_Name" at 570,-1074.34 h60
  text "GENERATED    :" at 2243,-1074.34 h60
  text ".Print_Date" at 3112.5,-1074.34 h60
  text ".Print_Time" at 3841.5,-1074.34 h60
  text "TEXAS INSTRUMENTS" at 5106,-1074.34 h60
M6 Assembly Bottom:
  lines w10: -299.5,-737.33 6302.5,-737.33 ; -297.5,-940.67 6302.5,-940.67 ; 1108.5,-1150.5 1108.5,-947.67 ; 1730.5,-737.33 1730.5,-534 ; 2570.5,-737.33 2570.5,-534 ; 3837.5,-1144 3837.5,-534 ; 4726.5,-1144 6302,-1144 6302,-534 -299.5,-534 -299.5,-1144 2297.5,-1144 6302.5,-1144 6302.5,-534
  text "COMPONENTS MARKED 'DNP' SHOULD NOT BE POPULATED." at 6095,-328 h60
  text ".VariantName" at 5051,-444 h60
  text "ASSEMBLY VARIANT:" at 6090,-444 h60
  text ".VersionControl_RevNumber" at 1028.5,-666.17 h60
  text "SVN REV:" at 1534.5,-666.17 h60
  text ".PCB_Rev" at 2081,-666.17 h60
  text "REV:" at 2372.5,-666.17 h60
  text ".PRJ_Number" at 3217,-666.17 h60
  text "BOARD #:" at 3762.5,-666.17 h60
  text "PCB VIEWED FROM BOTTOM SIDE" at 6239,-666.17 h60
  text ".TID" at 3217,-869.5 h60
  text "TID #:" at 3762.5,-869.5 h60
  text "TEXAS INSTRUMENTS" at 897.5,-1074.84 h60
  text ".Print_Time" at 2162,-1074.84 h60
  text ".Print_Date" at 2891,-1074.84 h60
  text "GENERATED    :" at 3760.5,-1074.84 h60
  text ".plot_File_Name" at 5433.5,-1074.84 h60
  text "PLOT NAME =" at 6239,-1074.84 h60
M9 Title Sheet:
  drawing of 57 lines, arcs and shapes, not listed
  text "1" at 732.84,8026.5 h70
  text "2" at 3228.5,8026.5 h70
  text "3" at 5717.84,8026.5 h70
  text "4" at 8224.51,8026.5 h70
  text "5" at 10723.5,8026.5 h70
  text "6" at 13228.5,8026.5 h70
  text "A" at -423.5,6883.5 h70
  text "A" at 14376.5,6883.5 h70
  text "B" at -423.5,4503.5 h70
  text "B" at 14376.5,4503.5 h70
  text "C" at -423.5,2128.5 h70
  text "C" at 14376.5,2128.5 h70
  text "PROJECT TITLE:" at 11336.5,267.5 h45
  text ".PRJ_Title" at 11386.5,134.17 h70
  text "DESIGNED FOR:" at 11336.5,-33.5 h45
  text ".PRJ_Customer" at 11386.5,-173.5 h70
  text "D" at -423.5,-241.5 h70
  text "D" at 14376.5,-241.5 h70
  text "FILE NAME:" at 11336.5,-333.5 h45
  text ".PCB_File_Name_No_Path" at 11386.5,-453.5 h70
  text "Texas Instruments (TI) and/or its licensors do not warrant the accuracy or completeness of this specification" at 6367,-615.34 h45
  text "ENGINEER:" at 11336.5,-623.5 h45
  text "LAYOUT BY:" at 12841.5,-623.5 h45
  text "or any information contained therein. TI and/or its licensors do not warrant that this design will meet" at 6322.01,-728 h45
  text "Ruby.Li" at 11386.5,-778.49 h70
  text "Ruby.Li" at 12892,-778.49 h70
  text "the specifications, will be suitable for your application or fit for any particular purpose, or will operate in" at 6322.01,-840.67 h45
  text ".Layer_Name" at 570,-868.49 h60
  text "ALTIUM DESIGNER VERSION:" at 12841.5,-933.5 h45
  text "an implementation. TI and/or its licensors do not warrant that the design is production worthy. You should" at 6322.01,-953.33 h45
  text "completely validate and test your design implementation to confirm the system functionality for your application." at 6367,-1066 h45
  text ".print_Scale" at 11386.5,-1066.83 h70
  text ".Application_BuildNumber" at 12892,-1066.83 h70
  text "1" at 732.84,-1273.5 h70
  text "2" at 3228.5,-1273.5 h70
  text "3" at 5717.84,-1273.5 h70
  text "4" at 8224.51,-1273.5 h70
  text "5" at 10723.5,-1273.5 h70
  text "6" at 13228.5,-1273.5 h70
M10 Fab Notes:
  drawing of 173 lines, arcs and shapes, not listed
  text "DESIGN INFORMATION" at 12371.02,6191 h60
  text "MIN. TRACK WIDTH:" at 11726.46,6011 h60
  text "8" at 12822.7,6011 h60
  text "MIL" at 12977.46,6011 h60
  text "MIN. CLEARANCE:" at 11726.46,5879 h60
  text "0.2" at 12762.7,5879 h60
  text "mm" at 12977.46,5879 h60
  text "MIN. VIA PAD SIZE:" at 11726.46,5747 h60
  text "24" at 12792.71,5747 h60
  text "MIL" at 12977.46,5747 h60
  text "0.05mm (2MIL)" at 12421.46,5605.29 h60
  text "MINIMUM ANNULAR RING" at 11397.23,5601 h60
  text "EXTERNAL" at 13129.46,5601 h60
  text "PER" at 11597.23,5483 h60
  text "IPC-D-275 CLASS 2 LEVEL C" at 11817.23,5483 h60
  text "MIL, HOLES" at 13305.46,5370.71 h60
  text "+/-" at 12913,5370 h60
  text "+/-" at 13767,5370 h60
  text "REGISTRATION TOLERANCES:" at 11397.23,5365 h60
  text "METAL" at 12597,5365 h60
  text "5" at 13173.2,5365 h60
  text "3" at 14006.2,5365 h60
  text "MIL" at 14122.46,5365 h60
  text "+/-" at 13767,5252 h60
  text "HOLE SIZE TOLERANCE (UNLESS OTHERWISE SPECIFIED):" at 11397.23,5247 h60
  text "3" at 14006.2,5247 h60
  text "MIL" at 14122.46,5247 h60
  text "MATERIAL:" at 11322.46,5037.54 h60
  text "FR-4 High Tg" at 12308.9,4897.21 h60
  text "FR-408" at 11743.46,4888.64 h60
  text "OTHER" at 13231.46,4888.64 h60
  text "X" at 12154,4885 h60
  text "62 MIL (1.6mm) +/-10%" at 12063.56,4725.92 h60
  text "THICKNESS:" at 11397.23,4721.64 h60
  text "X" at 11935.4,4721.64 h60
  text "OTHER" at 13348.46,4721.64 h60
  text "TOLERANCE:" at 11397.23,4563.64 h60
  text "X" at 12236.53,4563.64 h60
  text "ANSI IPC-6012 TYPE 3 CLASS 2" at 12423.48,4563.64 h60
  text "OTHER +/-" at 12423.46,4407.64 h60
  text "BOW & TWIST:" at 11397.23,4250.64 h60
  text "X" at 12236.53,4250.64 h60
  text "ANSI IPC-6012 TYPE 3 CLASS 2" at 12423.48,4250.64 h60
  text "OTHER +/-" at 12423.46,4092.13 h60
  text "DRILLING:" at 11322.46,3953.64 h60
  text "REFERENCE:" at 11397.23,3836.64 h60
  text "X" at 12045.46,3836.64 h60
  text "AS SHOWN" at 12232.46,3836.64 h60
  text "X" at 12946.46,3836.64 h60
  text "NC_DRILL FILES" at 13083.46,3836.64 h60
  text "PTH COPPER THICKNESS:" at 11397.23,3678.64 h60
  text "X" at 12527.46,3678.64 h60
  text "20-30 um" at 12664.46,3678.64 h60
  text "OTHER" at 13381.46,3678.64 h60
  text "BOARD FINISH:" at 11322.46,3519.64 h60
  text "SILKSCREEN:" at 11477.68,3401.64 h60
  text "X" at 12426.46,3401.64 h60
  text "TOP" at 12552.46,3401.64 h60
  text "X" at 12936.46,3401.64 h60
  text "BOTTOM" at 13063.46,3401.64 h60
  text "SILKSCREEN COLOR:" at 11477.68,3234.64 h60
  text "X" at 12425.42,3234.64 h60
  text "WHITE" at 12552.46,3234.64 h60
  text "OTHER" at 13063.46,3234.64 h60
  text "X" at 12556.42,3075.44 h60
  text "GREEN" at 12683.46,3075.44 h60
  text "OTHER" at 13301.46,3075.44 h60
  text "SOLDER RESIST COLOR:" at 11477.68,3064.64 h60
  text "X" at 12556.42,2905.44 h60
  text "MATTE" at 12683.46,2905.44 h60
  text "SEMI-GLOSS" at 13301,2904.8 h60
  text "IMMERSION GOLD (ENIG)" at 12383.46,2716.92 h60
  text "ENEPIG" at 13721,2713.64 h60
  text "SURFACE FINISH:" at 11322.46,2712.64 h60
  text "X" at 12196.51,2712.64 h60
  text "IMM. TIN/SILVER OR EQUIV" at 11652,2555.64 h60
  text "OTHER" at 13083.46,2555.64 h60
  text "ARRAY/PANEL:" at 11322.46,2376.64 h60
  text "CUT AND TRIM PER M1 BOARD OUTLINE" at 12383.46,2372.35 h60
  text "N.C. ROUTE" at 12383.46,2220.64 h60
  text "X" at 13062.46,2220.64 h60
  text "V. SCORE" at 13249.46,2220.64 h60
  text "CERTIFICATION:" at 11322.46,2083.64 h60
  text "MATERIALS AND WORKMANSHIP FOR ALL PCBS" at 12047.46,2083.64 h60
  text "TO MEET OR EXCEED THE REQUIREMENTS OF:" at 12047.46,1985.64 h60
  text "X" at 11673.96,1849.13 h60
  text "ANSI IPC-A-600F CLASS ->" at 11812.96,1849.13 h60
  text "X" at 13452.02,1849.13 h60
  text "2" at 13570.96,1849.14 h60
  text "1" at 13255.96,1847.64 h60
  text "3" at 13924.96,1847.64 h60
  text "X" at 12488.02,1689.64 h60
  text "RoHS" at 12624.96,1689.64 h60
  text "OTHER" at 13269.36,1689.64 h60
  text "PER ORDER" at 13666.42,1689.64 h60
  text "ALL BOARDS MUST MEET OR EXCEED UL94-V0 REQUIREMENTS." at 11350,1524 h60
  text "PCB MUST BEAR THE UL94V-0 UL REGISTERED MATERIAL ID NUMBER" at 11350,1404 h60
  text "ADDITIONAL REQUIREMENTS:" at 11322.46,1230.64 h60
  text "MICROSECTION:" at 11397.23,1115.64 h60
  text "YES" at 12302.96,1115.64 h60
  text "REQUIRED" at 13164.46,959.49 h60
  text "BARE BOARD ELEC. TEST:" at 11397.23,956.64 h60
  text "NONE" at 12702.96,956.64 h60
  text "X" at 13037.46,956.64 h60
  text "PER ORDER" at 13756.46,956.64 h60
  text ".Layer_Name" at 570,-868.49 h60
M11 Gerber Information:
  lines w10: -299,-940.17 6301,-940.17 ; -299,-736.83 6303,-736.83 ; -299,-533.5 -299,-1143.5 3706,-1143.5 6303,-1143.5 6303,-533.5 -298.5,-533.5 -298.5,-1143.5 1277,-1143.5 ; 2166,-1143.5 2166,-533.5 ; 3433,-736.83 3433,-533.5 ; 4273,-736.83 4273,-533.5 ; 4895,-1150 4895,-947.17
  text "ALL ARTWORK VIEWED FROM TOP SIDE" at -235.5,-665.67 h60
  text "BOARD #:" at 2241,-665.67 h60
  text ".PRJ_Number" at 2786.5,-665.67 h60
  text "REV:" at 3631,-665.67 h60
  text ".PCB_Rev" at 3922.5,-665.67 h60
  text "SVN REV:" at 4469,-665.67 h60
  text ".VersionControl_RevNumber" at 4975,-665.67 h60
  text "LAYER NAME =" at -235.5,-868.49 h60
  text "TID #:" at 2241,-869 h60
  text ".TID" at 2786.5,-869 h60
  text "PLOT NAME =" at -235.5,-1074.34 h60
  text ".plot_File_Name" at 570,-1074.34 h60
  text "GENERATED    :" at 2243,-1074.34 h60
  text ".Print_Date" at 3112.5,-1074.34 h60
  text ".Print_Time" at 3841.5,-1074.34 h60
  text "TEXAS INSTRUMENTS" at 5106,-1074.34 h60
M12 Stackup:
  lines w1: 5869.1,2504.94 5946.66,2582.5 6066.66,2702.5 6186.66,2822.5 6306.66,2942.5 6426.66,3062.5 ; 5869.1,2564.94 5886.66,2582.5 6006.66,2702.5 6126.66,2822.5 6246.66,2942.5 6366.66,3062.5 6426.66,3122.5 ; 5869.1,2624.94 5946.66,2702.5 6066.66,2822.5 6186.66,2942.5 6306.66,3062.5 6426.66,3182.5 ; 5869.1,2684.94 5886.66,2702.5 6006.66,2822.5 6126.66,2942.5 6246.66,3062.5 6366.66,3182.5 ; 5869.1,2744.94 5946.66,2822.5 6066.66,2942.5 6186.66,3062.5 6306.66,3182.5 ; 5869.1,2804.94 5886.66,2822.5 6006.66,2942.5 6126.66,3062.5 6246.66,3182.5 ; 5869.1,2864.94 5946.66,2942.5 6066.66,3062.5 6186.66,3182.5 ; 5869.1,2924.94 5886.66,2942.5 6006.66,3062.5 6126.66,3182.5 ; 5869.1,2984.94 5946.66,3062.5 6066.66,3182.5 ; 5869.1,3044.94 5886.66,3062.5 6006.66,3182.5 ; 5869.1,3104.94 5946.66,3182.5 ; 5869.1,3164.94 5886.66,3182.5 ; 5886.66,2462.5 6006.66,2582.5 6126.66,2702.5 6246.66,2822.5 6366.66,2942.5 6426.66,3002.5 ; 5946.66,2462.5 6066.66,2582.5 6186.66,2702.5 6306.66,2822.5 6426.66,2942.5 ; 6006.66,2462.5 6126.66,2582.5 6246.66,2702.5 6366.66,2822.5 6426.66,2882.5 ; 6066.66,2462.5 6186.66,2582.5 6306.66,2702.5 6426.66,2822.5 ; 6126.66,2462.5 6246.66,2582.5 6366.66,2702.5 6426.66,2762.5 ; 6186.66,2462.5 6306.66,2582.5 6426.66,2702.5 ; 6246.66,2462.5 6366.66,2582.5 6426.66,2642.5 ; 6306.66,2462.5 6426.66,2582.5 ; 6366.66,2462.5 6426.66,2522.5
  lines w15: 4034.5,2582.5 4285.59,2582.5 4742.59,2582.5 5178.94,2582.5 5537.36,2582.5 5869.1,2582.5 6426.66,2582.5 ; 4034.5,2702.5 4285.59,2702.5 4742.59,2702.5 5178.94,2702.5 5537.36,2702.5 5869.1,2702.5 6426.66,2702.5 ; 4034.5,2822.5 4285.59,2822.5 4742.59,2822.5 5178.94,2822.5 5537.36,2822.5 5869.1,2822.5 6426.66,2822.5 ; 4034.5,2942.5 4285.59,2942.5 4742.59,2942.5 5178.94,2942.5 5537.36,2942.5 5869.1,2942.5 6426.66,2942.5 ; 4034.5,3062.5 4285.59,3062.5 4742.59,3062.5 5178.94,3062.5 5537.36,3062.5 5869.1,3062.5 6426.66,3062.5 ; 4034.5,3182.5 6426.66,3182.5 ; 4285.59,3302.5 4285.59,2462.5 ; 4742.59,3302.5 4742.59,2462.5 ; 5178.94,3302.5 5178.94,2462.5 ; 5537.36,3302.5 5537.36,2462.5 ; 5869.1,3302.5 5869.1,2462.5 ; 4285.59,2462.5 4034.5,2462.5 4034.5,3302.5 6426.66,3302.5 6426.66,2462.5 5869.1,2462.5 ; 4285.59,2462.5 4742.59,2462.5 ; 4742.59,2462.5 5178.94,2462.5 ; 5178.94,2462.5 5537.36,2462.5 ; 5537.36,2462.5 5869.1,2462.5
  text "Layer" at 4094.5,3212.5 h60
  text "Name" at 4345.59,3212.5 h60
  text "Material" at 4802.59,3212.5 h60
  text "Thickness" at 5238.94,3212.5 h60
  text "Constant" at 5597.36,3212.5 h60
  text "Board Layer Stack" at 5929.1,3212.5 h60
  text "1" at 4094.5,3092.5 h60
  text "Top Overlay" at 4345.59,3092.5 h60
  text "2" at 4094.5,2972.5 h60
  text "Top Solder" at 4345.59,2972.5 h60
  text "Solder Resist" at 4802.59,2972.5 h60
  text "0.40mil" at 5238.94,2972.5 h60
  text "3.5" at 5597.36,2972.5 h60
  text "3" at 4094.5,2852.5 h60
  text "Top Layer" at 4345.59,2852.5 h60
  text "Copper" at 4802.59,2852.5 h60
  text "2.80mil" at 5238.94,2852.5 h60
  text "4" at 4094.5,2732.5 h60
  text "Dielectric1" at 4345.59,2732.5 h60
  text "FR-4 High Tg" at 4802.59,2732.5 h60
  text "55.60mil" at 5238.94,2732.5 h60
  text "4.8" at 5597.36,2732.5 h60
  text "5" at 4094.5,2612.5 h60
  text "Bottom Layer" at 4345.59,2612.5 h60
  text "Copper" at 4802.59,2612.5 h60
  text "2.80mil" at 5238.94,2612.5 h60
  text "6" at 4094.5,2492.5 h60
  text "Bottom Solder" at 4345.59,2492.5 h60
  text "Solder Resist" at 4802.59,2492.5 h60
  text "0.40mil" at 5238.94,2492.5 h60
  text "3.5" at 5597.36,2492.5 h60
  text ".Layer_Name" at 570,-868.49 h60
M13 Component Bodies Top:
  text ".Layer_Name" at 570,-868.49 h60
M14 Component Bodies Bottom:
  text ".Layer_Name" at 570,-868.49 h60
M15 Courtyards Top:
  text ".Layer_Name" at 570,-868.49 h60
M16 Courtyards Bottom:
  text ".Layer_Name" at 570,-868.49 h60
